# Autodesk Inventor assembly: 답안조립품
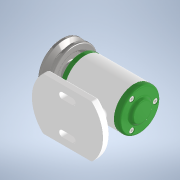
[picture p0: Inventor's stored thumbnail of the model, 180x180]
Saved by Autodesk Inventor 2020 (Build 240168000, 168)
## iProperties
Created: 2022-02
Part Number: 답안조립품
Document SubType Name: Assembly
Designer: 602-01
Author: 602-01
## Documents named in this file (14)
- C:\Users\602-01\Desktop\720206V1024\답안조립품.iam
- C:\Users\602-01\Desktop\720206V1024\본체.ipt
- C:\Users\602-01\Desktop\720206V1024\뒤커버.ipt
- C:\Users\602-01\Desktop\720206V1024\앞커버.ipt
- C:\Users\602-01\Desktop\720206V1024\축.ipt
- C:\Users\602-01\Desktop\720206V1024\베어링 6002.ipt
- C:\Users\602-01\Desktop\720206V1024\오일 실 15 x 25 x 7.ipt
- C:\Users\602-01\Desktop\720206V1024\V벨트풀리.ipt
- C:\Users\602-01\Desktop\720206V1024\키 3 x 3 x 12.ipt
- C:\Users\602-01\Desktop\720206V1024\평와셔 8 x 17.ipt
- C:\Users\602-01\Desktop\720206V1024\스프링와셔 8.ipt
- C:\Users\602-01\Desktop\720206V1024\너트 M8.ipt
- C:\Users\602-01\Desktop\720206V1024\볼트 M4 x 10.ipt
- C:\Users\602-01\Desktop\720206V1024\고무 캡.ipt
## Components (2 placed, 2 different names)
1. V벨트풀리:1
2. 고무 캡:1 — 각도:1
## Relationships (1: Angle 1)
- 각도:1 [Angle]: 고무 캡:1
